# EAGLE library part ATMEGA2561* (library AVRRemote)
MICROCONTROLLER 256 Kbytes FLASH 4 Kbytes EEPROM 8 Kbytes SRAM 54 General Purpose I/O pins 6-channels 16-bit PWM 2 x Serial USARTs 8-channels 10-bit A/D
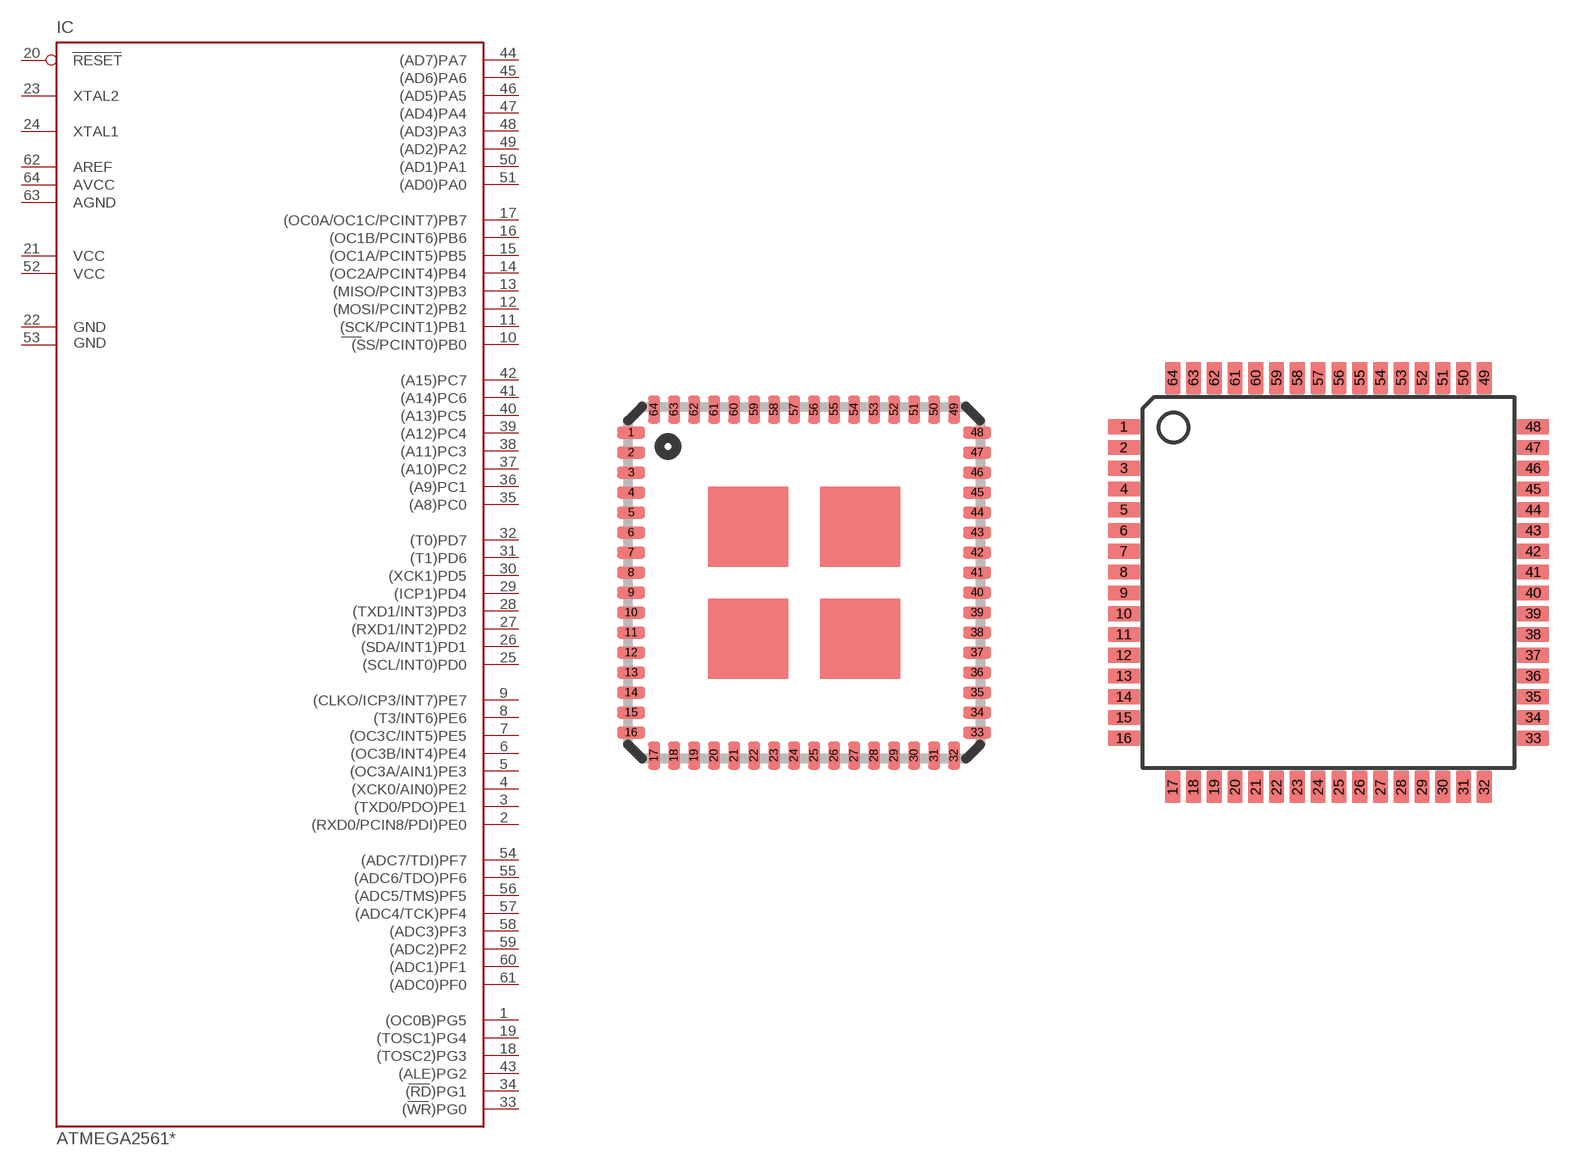
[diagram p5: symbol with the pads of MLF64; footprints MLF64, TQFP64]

Designator prefix IC

## ATMEGA2561-16MI, ATMEGA2561V-8MI  [MLF64]
1  (OC0B)PG5
2  (RXD0/PCIN8/PDI)PE0
3  (TXD0/PDO)PE1
4  (XCK0/AIN0)PE2
5  (OC3A/AIN1)PE3
6  (OC3B/INT4)PE4
7  (OC3C/INT5)PE5
8  (T3/INT6)PE6
9  (CLKO/ICP3/INT7)PE7
10  (SS/PCINT0)PB0
11  (SCK/PCINT1)PB1
12  (MOSI/PCINT2)PB2
13  (MISO/PCINT3)PB3
14  (OC2A/PCINT4)PB4
15  (OC1A/PCINT5)PB5
16  (OC1B/PCINT6)PB6
17  (OC0A/OC1C/PCINT7)PB7
18  (TOSC2)PG3
19  (TOSC1)PG4
20  RESET  in
21  VCC  pwr
22  GND  pwr
23  XTAL2  out
24  XTAL1  in
25  (SCL/INT0)PD0
26  (SDA/INT1)PD1
27  (RXD1/INT2)PD2
28  (TXD1/INT3)PD3
29  (ICP1)PD4
30  (XCK1)PD5
31  (T1)PD6
32  (T0)PD7
33  (WR)PG0
34  (RD)PG1
35  (A8)PC0
36  (A9)PC1
37  (A10)PC2
38  (A11)PC3
39  (A12)PC4
40  (A13)PC5
41  (A14)PC6
42  (A15)PC7
43  (ALE)PG2
44  (AD7)PA7
45  (AD6)PA6
46  (AD5)PA5
47  (AD4)PA4
48  (AD3)PA3
49  (AD2)PA2
50  (AD1)PA1
51  (AD0)PA0
52  VCC1  pwr
53  GND1  pwr
54  (ADC7/TDI)PF7
55  (ADC6/TDO)PF6
56  (ADC5/TMS)PF5
57  (ADC4/TCK)PF4
58  (ADC3)PF3
59  (ADC2)PF2
60  (ADC1)PF1
61  (ADC0)PF0
62  AREF
63  AGND  pwr
64  AVCC  pwr

## ATMEGA2561-16MU, ATMEGA2561V-8MU  [MLF64]
Pads as for MLF64

## ATMEGA2561-16AI, ATMEGA2561V-8AI  [TQFP64]
Pads as for MLF64

## ATMEGA2561-16AU, ATMEGA2561V-8AU  [TQFP64]
Pads as for MLF64

## Footprint MLF64 (pad centres in mm)
64M1 Micro Lead Frame package (MLF)
smd 0.7 x 0.3: 1 -4.325,3.75; 2 -4.325,3.25; 3 -4.325,2.75; 4 -4.325,2.25; 5 -4.325,1.75; 6 -4.325,1.25; 7 -4.325,0.75; 8 -4.325,0.25; 9 -4.325,-0.25; 10 -4.325,-0.75; 11 -4.325,-1.25; 12 -4.325,-1.75; 13 -4.325,-2.25; 14 -4.325,-2.75; 15 -4.325,-3.25; 16 -4.325,-3.75; 33 4.325,-3.75; 34 4.325,-3.25; 35 4.325,-2.75; 36 4.325,-2.25; 37 4.325,-1.75; 38 4.325,-1.25; 39 4.325,-0.75; 40 4.325,-0.25; 41 4.325,0.25; 42 4.325,0.75; 43 4.325,1.25; 44 4.325,1.75; 45 4.325,2.25; 46 4.325,2.75; 47 4.325,3.25; 48 4.325,3.75
smd 0.3 x 0.7: 17 -3.75,-4.325; 18 -3.25,-4.325; 19 -2.75,-4.325; 20 -2.25,-4.325; 21 -1.75,-4.325; 22 -1.25,-4.325; 23 -0.75,-4.325; 24 -0.25,-4.325; 25 0.25,-4.325; 26 0.75,-4.325; 27 1.25,-4.325; 28 1.75,-4.325; 29 2.25,-4.325; 30 2.75,-4.325; 31 3.25,-4.325; 32 3.75,-4.325; 49 3.75,4.325; 50 3.25,4.325; 51 2.75,4.325; 52 2.25,4.325; 53 1.75,4.325; 54 1.25,4.325; 55 0.75,4.325; 56 0.25,4.325; 57 -0.25,4.325; 58 -0.75,4.325; 59 -1.25,4.325; 60 -1.75,4.325; 61 -2.25,4.325; 62 -2.75,4.325; 63 -3.25,4.325; 64 -3.75,4.325

## Footprint TQFP64 (pad centres in mm)
Thin Plasic Quad Flat Package
smd 1.194 x 0.559: 1 -7.76,5.905; 2 -7.76,5.118; 3 -7.76,4.331; 4 -7.76,3.543; 5 -7.76,2.756; 6 -7.76,1.968; 7 -7.76,1.181; 8 -7.76,0.394; 9 -7.76,-0.394; 10 -7.76,-1.181; 11 -7.76,-1.968; 12 -7.76,-2.756; 13 -7.76,-3.543; 14 -7.76,-4.331; 15 -7.76,-5.118; 16 -7.76,-5.905; 33 7.76,-5.905; 34 7.76,-5.118; 35 7.76,-4.331; 36 7.76,-3.543; 37 7.76,-2.756; 38 7.76,-1.968; 39 7.76,-1.181; 40 7.76,-0.394; 41 7.76,0.394; 42 7.76,1.181; 43 7.76,1.968; 44 7.76,2.756; 45 7.76,3.543; 46 7.76,4.331; 47 7.76,5.118; 48 7.76,5.905
smd 0.559 x 1.194: 17 -5.905,-7.76; 18 -5.118,-7.76; 19 -4.331,-7.76; 20 -3.543,-7.76; 21 -2.756,-7.76; 22 -1.968,-7.76; 23 -1.181,-7.76; 24 -0.394,-7.76; 25 0.394,-7.76; 26 1.181,-7.76; 27 1.968,-7.76; 28 2.756,-7.76; 29 3.543,-7.76; 30 4.331,-7.76; 31 5.118,-7.76; 32 5.905,-7.76; 49 5.905,7.76; 50 5.118,7.76; 51 4.331,7.76; 52 3.543,7.76; 53 2.756,7.76; 54 1.968,7.76; 55 1.181,7.76; 56 0.394,7.76; 57 -0.394,7.76; 58 -1.181,7.76; 59 -1.968,7.76; 60 -2.756,7.76; 61 -3.543,7.76; 62 -4.331,7.76; 63 -5.118,7.76; 64 -5.905,7.76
